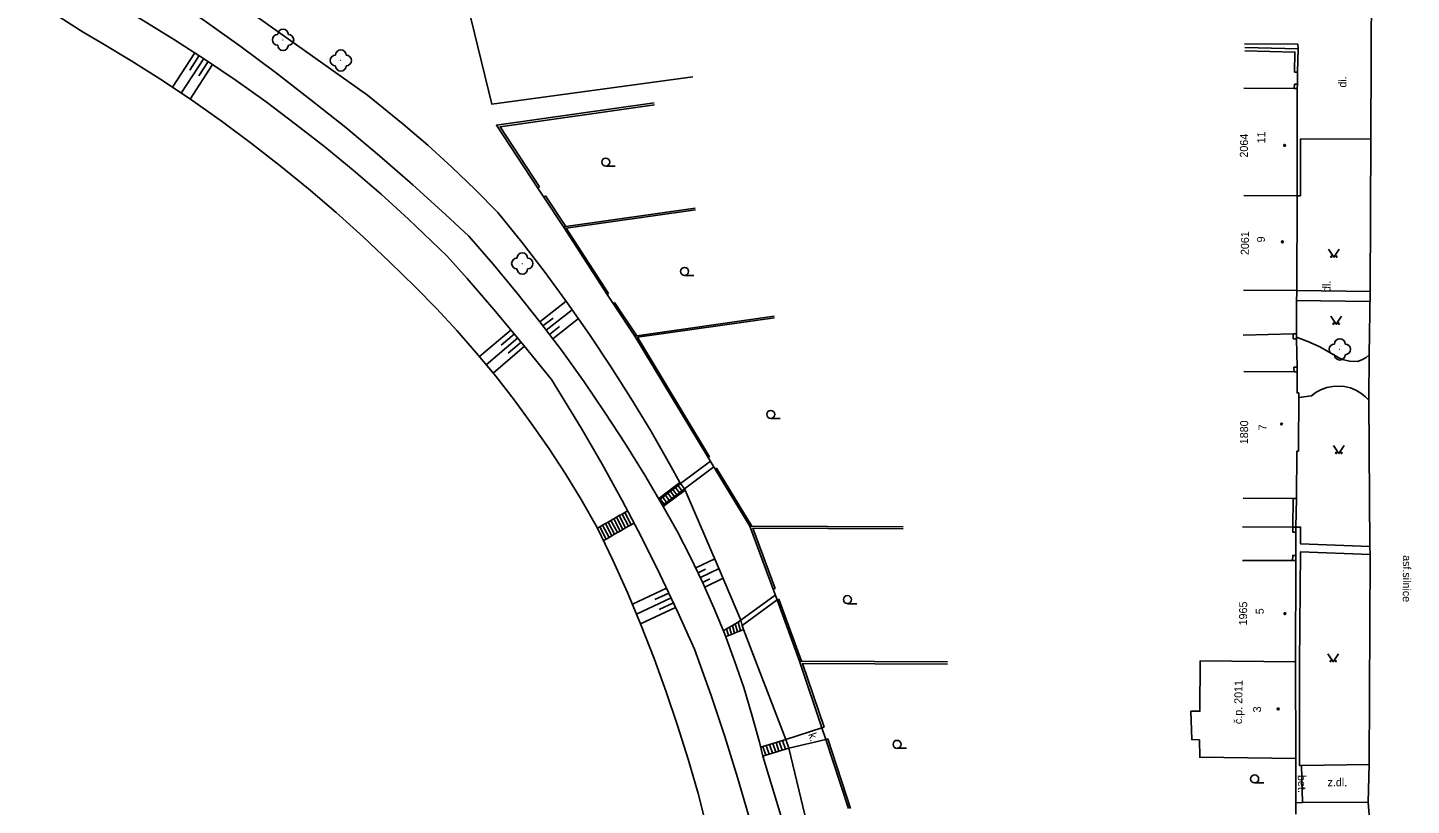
# Model space of a CAD drawing. Extents: x -584400 to -581602, y -1210894 to -1208793.
# Drawn here: x -582970.7 to -582841, y -1210250.4 to -1210177.5 of the extents above; entities that cross this region are included whole.
import ezdxf

# ---------------------------------------------------------------- set-up
doc = ezdxf.new("R2010")
doc.units = 0
for name, color, linetype in [('BUDOVY_MĚŘ', 7, 'Continuous'), ('BUDOVY_NEMĚŘ', 7, 'Continuous'), ('POMOC_POPIS', 7, 'Continuous'), ('ROZHRANÍ_PLOCH', 7, 'Continuous'), ('VÝŠKOPIS', 7, 'Continuous'), ('ZELEŇ', 7, 'Continuous'), ('ZN_BUDOV', 7, 'Continuous'), ('ZN_DOPLŇKOVÉ', 7, 'Continuous'), ('ZN_KULTUR', 7, 'Continuous'), ('Č_POPIS_EVID', 7, 'Continuous'), ('Č_POPIS_ORIENT', 7, 'Continuous')]:
    doc.layers.add(name, color=color, linetype=linetype)

msp = doc.modelspace()

# ---------------------------------------------------------------- linework, layer by layer
at = {"layer": 'BUDOVY_MĚŘ'}
for points in [[(-582851.69, -1210193.26), (-582851.67, -1210183.21), (-582851.97, -1210183.21), (-582856.67, -1210183.19)], [(-582851.69, -1210193.26), (-582856.69, -1210193.24)], [(-582851.72, -1210202.15), (-582851.69, -1210193.26)], [(-582851.72, -1210202.15), (-582856.72, -1210202.13)], [(-582851.57, -1210217.21), (-582851.54, -1210211.75), (-582851.7, -1210211.75), (-582851.69, -1210210.43), (-582851.68, -1210209.79), (-582851.98, -1210209.79), (-582856.68, -1210209.75)], [(-582851.76, -1210221.67), (-582851.73, -1210217.21)], [(-582851.57, -1210217.21), (-582851.73, -1210217.21)], [(-582851.76, -1210221.67), (-582852.06, -1210221.67), (-582856.76, -1210221.64)], [(-582851.84, -1210236.97), (-582851.81, -1210227.48), (-582852.11, -1210227.48), (-582856.81, -1210227.46)], [(-582851.81, -1210246.03), (-582851.84, -1210236.97)]]:
    msp.add_lwpolyline(points, dxfattribs=at)
at = {"layer": 'BUDOVY_NEMĚŘ'}
msp.add_lwpolyline([(-582851.81, -1210246.03), (-582860.82, -1210245.92), (-582860.84, -1210244.29), (-582861.57, -1210244.26), (-582861.64, -1210241.6), (-582860.8, -1210241.6), (-582860.78, -1210236.89), (-582851.84, -1210236.97)], dxfattribs=at)
at = {"layer": 'ROZHRANÍ_PLOCH'}
for points in [[(-582973.11, -1210164.21), (-582969.81, -1210166.52), (-582966.46, -1210168.78), (-582963.06, -1210170.96), (-582960.89, -1210172.31), (-582957.44, -1210174.57), (-582954.03, -1210176.9), (-582950.66, -1210179.3), (-582947.35, -1210181.76), (-582944.08, -1210184.29), (-582940.86, -1210186.88), (-582937.69, -1210189.53), (-582934.57, -1210192.24), (-582931.51, -1210195.01), (-582929.31, -1210197.07), (-582927.03, -1210199.69), (-582924.81, -1210202.37), (-582922.65, -1210205.1), (-582920.55, -1210207.88), (-582918.52, -1210210.71), (-582916.56, -1210213.58), (-582914.66, -1210216.5), (-582912.83, -1210219.46), (-582911.09, -1210222.41)], [(-582844.84, -1210202.24), (-582844.73, -1210173.24)], [(-582962.83, -1210175.09), (-582959.84, -1210176.83), (-582956.89, -1210178.64), (-582953.99, -1210180.51), (-582951.13, -1210182.45), (-582948.31, -1210184.46), (-582945.55, -1210186.54), (-582942.83, -1210188.67), (-582940.16, -1210190.87), (-582937.54, -1210193.13), (-582934.98, -1210195.45), (-582931.39, -1210198.89)], [(-582856.61, -1210179.01), (-582851.61, -1210179.06), (-582851.59, -1210179.5)], [(-582851.69, -1210193.26), (-582851.38, -1210193.26), (-582851.36, -1210187.93), (-582844.79, -1210187.97)], [(-582899.26, -1210267.34), (-582900.07, -1210263.4), (-582900.97, -1210259.47), (-582901.95, -1210255.56), (-582903, -1210251.67), (-582904.13, -1210247.81), (-582905.33, -1210243.96), (-582906.62, -1210240.14), (-582908.18, -1210235.79), (-582909.77, -1210232.25), (-582911.42, -1210228.75), (-582913.15, -1210225.28), (-582914.96, -1210221.85), (-582916.83, -1210218.45), (-582918.77, -1210215.1), (-582921.58, -1210210.51), (-582924.15, -1210207.3), (-582926.78, -1210204.14), (-582929.47, -1210201.03), (-582931.39, -1210198.89)], [(-582851.72, -1210202.15), (-582844.84, -1210202.24)], [(-582844.93, -1210208.19), (-582844.84, -1210202.24)], [(-582851.74, -1210203.1), (-582844.86, -1210203.19)], [(-582851.76, -1210206.52), (-582850.68, -1210206.93), (-582849.63, -1210207.41), (-582848.25, -1210208.18), (-582847.79, -1210208.45), (-582847.3, -1210208.65), (-582846.78, -1210208.77), (-582846.02, -1210208.8), (-582845.61, -1210208.66), (-582845.23, -1210208.44), (-582844.93, -1210208.19)], [(-582844.96, -1210212.44), (-582844.93, -1210208.19)], [(-582850.35, -1210212.02), (-582849.91, -1210211.7), (-582849.42, -1210211.44), (-582848.89, -1210211.25), (-582848.35, -1210211.14), (-582847.8, -1210211.11), (-582847.24, -1210211.16), (-582846.7, -1210211.29), (-582846.19, -1210211.5), (-582845.71, -1210211.78), (-582845.27, -1210212.12), (-582844.96, -1210212.44)], [(-582850.35, -1210212.02), (-582851.54, -1210212.17)], [(-582844.86, -1210226.16), (-582844.96, -1210212.44)], [(-582909.47, -1210220.25), (-582906.68, -1210218.16)], [(-582909.11, -1210220.75), (-582906.36, -1210218.69)], [(-582911.52, -1210221.66), (-582909.55, -1210220.15)], [(-582910.42, -1210220.98), (-582910.19, -1210220.8)], [(-582910.19, -1210220.8), (-582909.95, -1210220.62)], [(-582910.19, -1210220.8), (-582909.82, -1210221.3)], [(-582909.95, -1210220.62), (-582909.71, -1210220.44)], [(-582909.95, -1210220.62), (-582909.59, -1210221.12)], [(-582909.71, -1210220.44), (-582909.47, -1210220.25)], [(-582909.71, -1210220.44), (-582909.35, -1210220.93)], [(-582909.55, -1210220.15), (-582909.47, -1210220.25)], [(-582909.47, -1210220.25), (-582909.11, -1210220.75)], [(-582909.11, -1210220.75), (-582909.35, -1210220.93)], [(-582909.11, -1210220.75), (-582909.03, -1210220.86)], [(-582911.46, -1210221.77), (-582911.38, -1210221.71)], [(-582911.38, -1210221.71), (-582911.14, -1210221.53)], [(-582911.38, -1210221.71), (-582911.02, -1210222.2)], [(-582911.14, -1210221.53), (-582910.9, -1210221.35)], [(-582911.14, -1210221.53), (-582910.78, -1210222.02)], [(-582909.03, -1210220.86), (-582911.09, -1210222.41)], [(-582910.78, -1210222.02), (-582911.02, -1210222.2)], [(-582910.9, -1210221.35), (-582910.66, -1210221.16)], [(-582910.9, -1210221.35), (-582910.54, -1210221.84)], [(-582910.54, -1210221.84), (-582910.78, -1210222.02)], [(-582910.66, -1210221.16), (-582910.42, -1210220.98)], [(-582910.66, -1210221.16), (-582910.3, -1210221.66)], [(-582910.3, -1210221.66), (-582910.54, -1210221.84)], [(-582910.42, -1210220.98), (-582910.06, -1210221.48)], [(-582910.06, -1210221.48), (-582910.3, -1210221.66)], [(-582909.82, -1210221.3), (-582910.06, -1210221.48)], [(-582909.59, -1210221.12), (-582909.82, -1210221.3)], [(-582909.35, -1210220.93), (-582909.59, -1210221.12)], [(-582915.74, -1210223.56), (-582915.48, -1210223.41)], [(-582915.48, -1210223.41), (-582915.22, -1210223.26)], [(-582915.48, -1210223.41), (-582914.88, -1210224.56)], [(-582915.22, -1210223.26), (-582914.96, -1210223.11)], [(-582915.22, -1210223.26), (-582914.62, -1210224.41)], [(-582914.96, -1210223.11), (-582914.7, -1210222.96)], [(-582914.96, -1210223.11), (-582914.36, -1210224.26)], [(-582914.7, -1210222.96), (-582914.44, -1210222.81)], [(-582914.7, -1210222.96), (-582914.1, -1210224.11)], [(-582911.02, -1210222.2), (-582911.15, -1210222.3)], [(-582911.09, -1210222.41), (-582909.8, -1210224.73), (-582908.57, -1210227.1), (-582907.42, -1210229.49), (-582906.35, -1210231.92), (-582905.34, -1210234.38), (-582904.41, -1210236.88), (-582903.56, -1210239.39), (-582902.78, -1210241.94), (-582902.08, -1210244.5), (-582901.76, -1210245.81)], [(-582917.26, -1210224.44), (-582917.04, -1210224.31)], [(-582917.04, -1210224.31), (-582916.78, -1210224.16)], [(-582917.04, -1210224.31), (-582916.44, -1210225.46)], [(-582916.78, -1210224.16), (-582916.52, -1210224.01)], [(-582916.78, -1210224.16), (-582916.18, -1210225.31)], [(-582916.52, -1210224.01), (-582916.26, -1210223.86)], [(-582916.52, -1210224.01), (-582915.92, -1210225.16)], [(-582916.26, -1210223.86), (-582916, -1210223.71)], [(-582916.26, -1210223.86), (-582915.66, -1210225.01)], [(-582916, -1210223.71), (-582915.74, -1210223.56)], [(-582916, -1210223.71), (-582915.4, -1210224.86)], [(-582915.74, -1210223.56), (-582915.14, -1210224.71)], [(-582915.14, -1210224.71), (-582914.88, -1210224.56)], [(-582914.88, -1210224.56), (-582914.62, -1210224.41)], [(-582914.62, -1210224.41), (-582914.36, -1210224.26)], [(-582914.36, -1210224.26), (-582914.1, -1210224.11)], [(-582914.1, -1210224.11), (-582913.84, -1210223.96)], [(-582851.8, -1210224.34), (-582851.36, -1210224.34), (-582851.37, -1210225.91), (-582844.86, -1210226.16)], [(-582916.69, -1210225.61), (-582916.44, -1210225.46)], [(-582916.44, -1210225.46), (-582916.18, -1210225.31)], [(-582916.18, -1210225.31), (-582915.92, -1210225.16)], [(-582915.92, -1210225.16), (-582915.66, -1210225.01)], [(-582915.66, -1210225.01), (-582915.4, -1210224.86)], [(-582915.4, -1210224.86), (-582915.14, -1210224.71)], [(-582844.85, -1210226.9), (-582851.36, -1210226.65), (-582851.46, -1210237.16), (-582851.47, -1210246.69), (-582851.27, -1210246.69), (-582844.93, -1210246.59)], [(-582844.93, -1210246.59), (-582844.85, -1210226.9), (-582844.86, -1210226.16)], [(-582903.83, -1210233.08), (-582900.6, -1210230.72)], [(-582903.69, -1210233.55), (-582900.43, -1210231.17)], [(-582905.16, -1210233.89), (-582904.89, -1210233.73)], [(-582904.89, -1210233.73), (-582904.62, -1210233.56)], [(-582904.89, -1210233.73), (-582904.7, -1210234.4)], [(-582904.62, -1210233.56), (-582904.36, -1210233.4)], [(-582904.62, -1210233.56), (-582904.42, -1210234.28)], [(-582904.36, -1210233.4), (-582904.09, -1210233.24)], [(-582904.36, -1210233.4), (-582904.14, -1210234.17)], [(-582904.09, -1210233.24), (-582903.83, -1210233.08)], [(-582904.09, -1210233.24), (-582903.86, -1210234.06)], [(-582903.83, -1210233.08), (-582903.69, -1210233.55)], [(-582903.69, -1210233.55), (-582903.58, -1210233.95)], [(-582905.46, -1210234.08), (-582905.16, -1210233.89)], [(-582904.98, -1210234.51), (-582905.25, -1210234.62)], [(-582905.16, -1210233.89), (-582904.98, -1210234.51)], [(-582904.7, -1210234.4), (-582904.98, -1210234.51)], [(-582904.42, -1210234.28), (-582904.7, -1210234.4)], [(-582904.14, -1210234.17), (-582904.42, -1210234.28)], [(-582903.86, -1210234.06), (-582904.14, -1210234.17)], [(-582903.58, -1210233.95), (-582903.86, -1210234.06)], [(-582896.22, -1210243.15), (-582899.61, -1210244.27)], [(-582901.96, -1210244.98), (-582901.75, -1210244.91)], [(-582901.75, -1210244.91), (-582901.44, -1210244.82)], [(-582901.48, -1210245.73), (-582901.75, -1210244.91)], [(-582901.44, -1210244.82), (-582901.14, -1210244.73)], [(-582901.17, -1210245.63), (-582901.44, -1210244.82)], [(-582901.14, -1210244.73), (-582900.83, -1210244.64)], [(-582900.87, -1210245.54), (-582901.14, -1210244.73)], [(-582900.87, -1210245.54), (-582900.56, -1210245.44)], [(-582900.83, -1210244.64), (-582900.52, -1210244.54)], [(-582900.56, -1210245.44), (-582900.83, -1210244.64)], [(-582900.56, -1210245.44), (-582900.26, -1210245.35)], [(-582900.52, -1210244.54), (-582900.22, -1210244.45)], [(-582900.26, -1210245.35), (-582900.52, -1210244.54)], [(-582900.26, -1210245.35), (-582899.95, -1210245.26)], [(-582900.22, -1210244.45), (-582899.91, -1210244.36)], [(-582899.95, -1210245.26), (-582900.22, -1210244.45)], [(-582899.95, -1210245.26), (-582899.64, -1210245.17)], [(-582899.91, -1210244.36), (-582899.61, -1210244.27)], [(-582899.64, -1210245.17), (-582899.91, -1210244.36)], [(-582899.64, -1210245.17), (-582899.34, -1210245.08)], [(-582899.34, -1210245.08), (-582899.61, -1210244.27)], [(-582899.34, -1210245.08), (-582895.86, -1210244.25)], [(-582901.76, -1210245.81), (-582901.48, -1210245.73)], [(-582901.76, -1210245.81), (-582900.17, -1210251.08), (-582898.66, -1210256.37), (-582897.23, -1210261.68), (-582895.88, -1210267.01), (-582894.6, -1210272.36), (-582892.9, -1210280.09)], [(-582901.48, -1210245.73), (-582901.17, -1210245.63)], [(-582901.17, -1210245.63), (-582900.87, -1210245.54)], [(-582851.19, -1210250.15), (-582851.27, -1210246.69)], [(-582845.02, -1210250.13), (-582844.93, -1210246.59)], [(-582851.8, -1210250.18), (-582851.19, -1210250.15), (-582845.02, -1210250.13)], [(-582845.01, -1210268.77), (-582844.96, -1210254.88), (-582844.92, -1210251.72), (-582845.02, -1210250.13)]]:
    msp.add_lwpolyline(points, dxfattribs=at)
at = {"layer": 'VÝŠKOPIS'}
for points in [[(-582971.64, -1210160.64), (-582957.28, -1210170.72), (-582938.82, -1210183.84)], [(-582934.33, -1210201.85), (-582936.75, -1210199.45), (-582939.23, -1210197.12), (-582941.76, -1210194.84), (-582944.35, -1210192.62), (-582946.99, -1210190.46), (-582949.68, -1210188.37), (-582952.41, -1210186.34), (-582955.19, -1210184.37), (-582958.02, -1210182.47), (-582960.9, -1210180.64), (-582963.81, -1210178.88), (-582965.46, -1210177.92), (-582968.83, -1210175.78), (-582972.16, -1210173.57)], [(-582957.1, -1210183.08), (-582955.01, -1210179.85)], [(-582956.27, -1210183.64), (-582954.17, -1210180.39)], [(-582955.47, -1210181.48), (-582954.59, -1210180.12)], [(-582955.44, -1210184.2), (-582953.34, -1210180.95)], [(-582954.63, -1210182.03), (-582953.75, -1210180.67)], [(-582926.6, -1210194.84), (-582928.73, -1210192.68), (-582930.92, -1210190.58), (-582933.17, -1210188.53), (-582935.46, -1210186.55), (-582938.82, -1210183.84)], [(-582926.6, -1210194.84), (-582924.36, -1210197.62), (-582922.18, -1210200.46), (-582920.06, -1210203.34), (-582918.02, -1210206.27), (-582916.03, -1210209.25), (-582914.12, -1210212.26), (-582912.27, -1210215.32), (-582910.5, -1210218.42), (-582909.55, -1210220.15)], [(-582934.33, -1210201.85), (-582932.36, -1210203.85), (-582930.44, -1210205.91), (-582928.59, -1210208.03), (-582926.8, -1210210.2), (-582925.07, -1210212.41), (-582923.4, -1210214.68), (-582921.8, -1210216.99), (-582920.27, -1210219.34), (-582918.8, -1210221.74), (-582917.26, -1210224.43)], [(-582920.2, -1210203.15), (-582922.67, -1210205.08)], [(-582921.43, -1210204.74), (-582922.37, -1210205.47)], [(-582919.62, -1210203.97), (-582922.06, -1210205.87)], [(-582919.04, -1210204.79), (-582921.46, -1210206.67)], [(-582928.32, -1210208.35), (-582925.36, -1210205.83)], [(-582926.28, -1210207.27), (-582925.04, -1210206.22)], [(-582920.83, -1210205.54), (-582921.76, -1210206.27)], [(-582927.68, -1210209.12), (-582924.72, -1210206.6)], [(-582927.04, -1210209.89), (-582924.09, -1210207.37)], [(-582925.64, -1210208.04), (-582924.4, -1210206.99)], [(-582909.03, -1210220.86), (-582905.85, -1210228.27), (-582903.83, -1210233.08)], [(-582917.26, -1210224.44), (-582915.82, -1210227.44), (-582914.46, -1210230.48), (-582913.17, -1210233.55), (-582911.95, -1210236.65), (-582910.81, -1210239.78), (-582909.75, -1210242.93), (-582908.76, -1210246.11), (-582907.84, -1210249.32), (-582907.01, -1210252.54), (-582906.14, -1210256.26)], [(-582906.26, -1210227.3), (-582908.05, -1210228.17)], [(-582907.15, -1210228.29), (-582907.83, -1210228.62)], [(-582905.87, -1210228.22), (-582907.62, -1210229.07)], [(-582906.73, -1210229.2), (-582907.41, -1210229.53)], [(-582905.48, -1210229.14), (-582907.2, -1210229.98)], [(-582913.99, -1210231.57), (-582910.79, -1210230.07)], [(-582913.61, -1210232.49), (-582910.36, -1210230.98)], [(-582911.89, -1210231.14), (-582910.57, -1210230.52)], [(-582913.23, -1210233.42), (-582909.94, -1210231.88)], [(-582911.48, -1210232.05), (-582910.15, -1210231.43)], [(-582903.58, -1210233.95), (-582899.61, -1210244.27)], [(-582899.34, -1210245.08), (-582897.25, -1210253.67), (-582893.34, -1210268.61)]]:
    msp.add_lwpolyline(points, dxfattribs=at)
at = {"layer": 'ZELEŇ'}
msp.add_lwpolyline([(-582915.79, -1210203.36), (-582915.67, -1210203.27)], dxfattribs=at)
for centre in [(-582946.73, -1210178.65), (-582941.32, -1210180.58), (-582924.31, -1210199.62), (-582847.69, -1210207.67)]:
    msp.add_circle(centre, 0.0005, dxfattribs=at)
for centre, start, end in [((-582946.73, -1210178.15), 0, 180), ((-582947.23, -1210178.65), 90, 270), ((-582946.73, -1210179.15), 180, 360), ((-582946.23, -1210178.65), 270, 90), ((-582941.82, -1210180.58), 90, 270), ((-582941.32, -1210180.08), 0, 180), ((-582940.82, -1210180.58), 270, 90), ((-582941.32, -1210181.08), 180, 360), ((-582924.31, -1210199.12), 0, 180), ((-582924.81, -1210199.62), 90, 270), ((-582923.81, -1210199.62), 270, 90), ((-582924.31, -1210200.12), 180, 360), ((-582848.19, -1210207.67), 90, 270), ((-582847.69, -1210207.17), 0, 180), ((-582847.19, -1210207.67), 270, 90), ((-582847.69, -1210208.17), 180, 360)]:
    msp.add_arc(centre, 0.5, start, end, dxfattribs=at)
at = {"layer": 'ZN_BUDOV'}
for centre in [(-582852.86, -1210188.54), (-582853.07, -1210197.59), (-582853.14, -1210214.67), (-582852.83, -1210232.45), (-582853.46, -1210241.39)]:
    msp.add_circle(centre, 0.0875, dxfattribs=at)
at = {"layer": 'ZN_DOPLŇKOVÉ'}
for points in [[(-583056.57, -1210054.07), (-583048.98, -1210061.82), (-583041.52, -1210069.5), (-583020.8, -1210090.92), (-583001.61, -1210110.68), (-582976.04, -1210137.13), (-582958.7, -1210156.31), (-582942.37, -1210171.79), (-582930.4, -1210171.32), (-582927.16, -1210184.69), (-582908.32, -1210182.1)], [(-582851.95, -1210181.67), (-582851.9, -1210179.8), (-582856.6, -1210179.67)], [(-582856.59, -1210179.37), (-582851.59, -1210179.5), (-582851.65, -1210181.67)], [(-582851.95, -1210181.67), (-582851.65, -1210181.67)], [(-582851.65, -1210182.81), (-582851.65, -1210181.67)], [(-582851.95, -1210182.8), (-582851.97, -1210183.21)], [(-582851.95, -1210182.8), (-582851.65, -1210182.81), (-582851.67, -1210183.21)], [(-582911.96, -1210184.54), (-582926.73, -1210186.65), (-582922.86, -1210192.55), (-582922.69, -1210192.44)], [(-582911.91, -1210184.73), (-582926.39, -1210186.8), (-582922.69, -1210192.44)], [(-582922.86, -1210192.55), (-582922.3, -1210193.39)], [(-582920.46, -1210196.18), (-582922.3, -1210193.39), (-582922.14, -1210193.28)], [(-582922.14, -1210193.28), (-582920.24, -1210196.15)], [(-582920.24, -1210196.15), (-582908.1, -1210194.44)], [(-582908.08, -1210194.59), (-582920.2, -1210196.3), (-582916.22, -1210202.44)], [(-582916.34, -1210202.52), (-582920.46, -1210196.18), (-582920.24, -1210196.15)], [(-582916.34, -1210202.52), (-582916.22, -1210202.44)], [(-582916.34, -1210202.52), (-582915.79, -1210203.36)], [(-582851.74, -1210203.3), (-582851.72, -1210202.15)], [(-582913.75, -1210206.42), (-582915.79, -1210203.36)], [(-582915.67, -1210203.27), (-582913.58, -1210206.4)], [(-582851.76, -1210206.22), (-582851.74, -1210203.3)], [(-582913.58, -1210206.4), (-582900.7, -1210204.56)], [(-582900.68, -1210204.7), (-582913.5, -1210206.54), (-582906.75, -1210217.74)], [(-582906.88, -1210217.82), (-582913.75, -1210206.42), (-582913.58, -1210206.4)], [(-582852.06, -1210206.23), (-582856.76, -1210206.33)], [(-582852.06, -1210206.23), (-582852.05, -1210206.68), (-582851.75, -1210206.67), (-582851.76, -1210206.22), (-582852.06, -1210206.23)], [(-582851.68, -1210209.34), (-582851.75, -1210206.67)], [(-582851.99, -1210209.34), (-582851.68, -1210209.34)], [(-582851.99, -1210209.34), (-582851.98, -1210209.79)], [(-582851.68, -1210209.79), (-582851.68, -1210209.34)], [(-582906.88, -1210217.82), (-582906.75, -1210217.74)], [(-582906.88, -1210217.82), (-582906.24, -1210218.9)], [(-582902.99, -1210224.24), (-582906.24, -1210218.9), (-582906.11, -1210218.82)], [(-582906.11, -1210218.82), (-582902.81, -1210224.24)], [(-582852.06, -1210221.67), (-582852.1, -1210224.34)], [(-582851.76, -1210221.67), (-582851.8, -1210224.34)], [(-582900.79, -1210230.17), (-582902.99, -1210224.24), (-582902.81, -1210224.24)], [(-582902.81, -1210224.24), (-582888.62, -1210224.3)], [(-582888.62, -1210224.5), (-582902.7, -1210224.44), (-582900.6, -1210230.1)], [(-582856.8, -1210224.32), (-582852.1, -1210224.34)], [(-582851.8, -1210224.34), (-582851.8, -1210224.81), (-582852.1, -1210224.81)], [(-582852.1, -1210224.34), (-582851.8, -1210224.34)], [(-582852.1, -1210224.34), (-582852.1, -1210224.81)], [(-582851.8, -1210227.01), (-582851.8, -1210224.81)], [(-582852.11, -1210227.48), (-582852.1, -1210227), (-582851.8, -1210227.01)], [(-582851.81, -1210227.48), (-582851.8, -1210227.01)], [(-582900.79, -1210230.17), (-582900.6, -1210230.1)], [(-582900.79, -1210230.17), (-582900.43, -1210231.17)], [(-582898.34, -1210236.92), (-582900.43, -1210231.17), (-582900.25, -1210231.1)], [(-582900.25, -1210231.1), (-582898.13, -1210236.92)], [(-582896.22, -1210243.15), (-582898.34, -1210236.92), (-582898.13, -1210236.92)], [(-582898.13, -1210236.92), (-582884.46, -1210236.98)], [(-582884.46, -1210237.18), (-582898.06, -1210237.13), (-582896.03, -1210243.09)], [(-582896.22, -1210243.15), (-582896.03, -1210243.09)], [(-582896.22, -1210243.15), (-582895.86, -1210244.25)], [(-582893.75, -1210250.72), (-582895.86, -1210244.25), (-582895.67, -1210244.19)], [(-582893.54, -1210250.72), (-582895.67, -1210244.19)], [(-582851.8, -1210250.18), (-582851.81, -1210246.03)], [(-582851.81, -1210251.27), (-582851.8, -1210250.18)]]:
    msp.add_lwpolyline(points, dxfattribs=at)
at = {"layer": 'ZN_KULTUR'}
for p, q in [((-582916.49, -1210190.49), (-582915.61, -1210190.49)), ((-582909.1, -1210200.74), (-582908.22, -1210200.74)), ((-582901.02, -1210214.15), (-582900.15, -1210214.15)), ((-582893.83, -1210231.52), (-582892.95, -1210231.52)), ((-582889.18, -1210245.08), (-582888.31, -1210245.08)), ((-582855.67, -1210248.32), (-582854.8, -1210248.32))]:
    msp.add_line(p, q, dxfattribs=at)
for points in [[(-582848.74, -1210198.28), (-582848.24, -1210199.03), (-582847.74, -1210198.28)], [(-582848.53, -1210204.56), (-582848.03, -1210205.31), (-582847.53, -1210204.56)], [(-582848.28, -1210216.69), (-582847.78, -1210217.44), (-582847.28, -1210216.69)], [(-582848.8, -1210236.21), (-582848.3, -1210236.96), (-582847.8, -1210236.21)]]:
    msp.add_lwpolyline(points, dxfattribs=at)
for centre, radius in [((-582916.49, -1210190.11), 0.375), ((-582909.1, -1210200.36), 0.375), ((-582848.49, -1210198.98), 0.05), ((-582847.99, -1210198.98), 0.05), ((-582848.28, -1210205.26), 0.05), ((-582847.78, -1210205.26), 0.05), ((-582901.02, -1210213.77), 0.375), ((-582848.03, -1210217.39), 0.05), ((-582847.53, -1210217.39), 0.05), ((-582893.83, -1210231.14), 0.375), ((-582848.55, -1210236.91), 0.05), ((-582848.05, -1210236.91), 0.05), ((-582889.18, -1210244.71), 0.375), ((-582855.67, -1210247.95), 0.375)]:
    msp.add_circle(centre, radius, dxfattribs=at)

# ---------------------------------------------------------------- texts
at = {"layer": 'POMOC_POPIS'}
for s, rotation, p in [('dl.', 89.4168, (-582847.08, -1210183.12)), ('dl.', 89.607, (-582848.56, -1210202.3)), ('asf.silnice', 269.7672, (-582841.77, -1210226.97)), ('k.', 288.2243, (-582897.52, -1210243.77)), ('bet.', 271.2543, (-582851.63, -1210247.59))]:
    msp.add_text(s, height=0.75, rotation=rotation, dxfattribs=at).set_placement(p)
msp.add_text('z.dl.', height=0.75, dxfattribs=at).set_placement((-582848.84, -1210248.64))
at = {"layer": 'Č_POPIS_EVID'}
for s, rotation, p in [('2064', 89.3521, (-582856.31, -1210189.69)), ('11', 89.8575, (-582854.68, -1210188.36)), ('2061', 89.3521, (-582856.22, -1210198.83)), ('9', 89.7937, (-582854.71, -1210197.64)), ('1880', 89.3521, (-582856.3, -1210216.57)), ('7', 89.7063, (-582854.56, -1210215.27)), ('1965', 89.3521, (-582856.39, -1210233.56)), ('5', 89.819, (-582854.82, -1210232.51)), ('3', 89.4484, (-582855.08, -1210241.72))]:
    msp.add_text(s, height=0.75, rotation=rotation, dxfattribs=at).set_placement(p)
at = {"layer": 'Č_POPIS_ORIENT'}
msp.add_text('č.p. 2011', height=0.75, rotation=89.35, dxfattribs=at).set_placement((-582856.85, -1210242.81))

doc.saveas('drawing.dxf')
